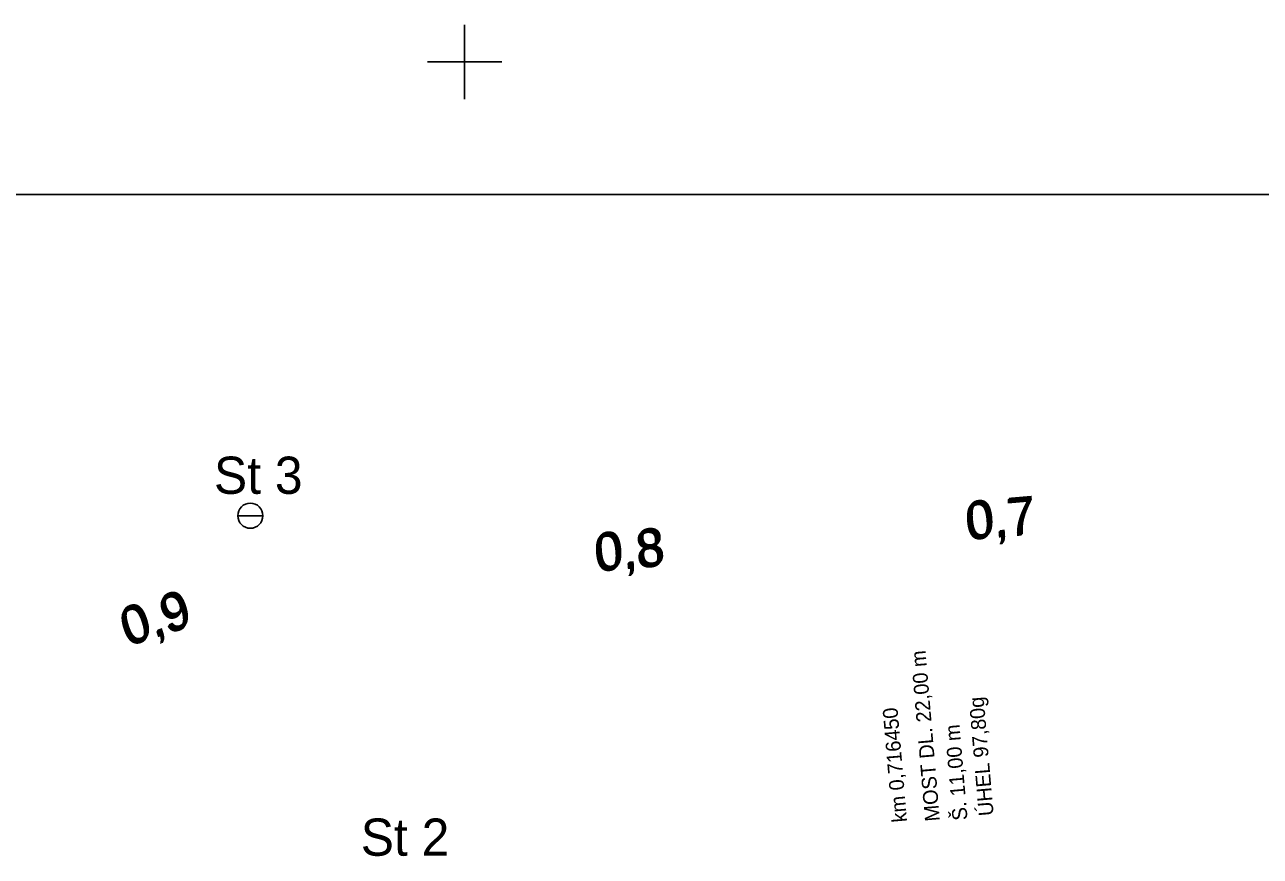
# Model space of a CAD drawing. Extents: x -606444 to -604546, y -1158114 to -1156869.
# Drawn here: x -605712.4 to -605380.6, y -1157092.1 to -1156868.7 of the extents above; entities that cross this region are included whole.
import ezdxf

# ---------------------------------------------------------------- set-up
doc = ezdxf.new("R2010")
doc.units = 0
for name, color, linetype in [('FORMAT', 7, 'Continuous'), ('Level 35', 7, 'Continuous'), ('NS_VB_POP', 7, 'Continuous'), ('OSAPOP', 7, 'Continuous'), ('ramecek_tisk', 7, 'Continuous'), ('studny', 7, 'Continuous')]:
    doc.layers.add(name, color=color, linetype=linetype)

# ---------------------------------------------------------------- blocks, each defined once
blk = doc.blocks.new('8.11')
at = {"layer": 'Level 35'}
blk.add_line((-0.0375, 0), (0.0375, 0), dxfattribs=at)
blk.add_circle((0, 0), 0.0375, dxfattribs=at)

msp = doc.modelspace()

# ---------------------------------------------------------------- linework, layer by layer
at = {"layer": 'FORMAT'}
for p, q in [((-605594.31, -1156888.73), (-605594.31, -1156868.73)), ((-605604.31, -1156878.73), (-605584.31, -1156878.73))]:
    msp.add_line(p, q, dxfattribs=at)
at = {"layer": 'ramecek_tisk'}
msp.add_line((-606362.25, -1156914.34), (-604562.25, -1156914.34), dxfattribs=at)

# ---------------------------------------------------------------- block references
at = {"layer": 'studny', "xscale": 90, "yscale": 90}
msp.add_blockref('8.11', (-605651.85, -1157000.63), dxfattribs=at)

# ---------------------------------------------------------------- texts
at = {"layer": 'NS_VB_POP'}
for s, p in [('MOST DL. 22,00 m', (-605466.66, -1157082.57)), ('ÚHEL 97,80g', (-605452.23, -1157081.11)), ('km 0,716450', (-605475.47, -1157082.82)), ('Š. 11,00 m', (-605459.24, -1157082.32))]:
    msp.add_text(s, height=4, rotation=94.8613, dxfattribs=at).set_placement(p)
at = {"layer": 'OSAPOP'}
for s, rotation, p in [('0,7', 4.8613, (-605459.47, -1157007.23)), ('0,7', 4.8613, (-605459.33, -1157007.07)), ('0,7', 4.8613, (-605459.2, -1157006.91)), ('0,7', 4.8613, (-605459.06, -1157006.75)), ('0,8', 4.8613, (-605558.84, -1157015.38)), ('0,8', 4.8613, (-605558.7, -1157015.22)), ('0,8', 4.8613, (-605559.11, -1157015.71)), ('0,8', 4.8613, (-605558.98, -1157015.54)), ('0,9', 17.6766, (-605684.9, -1157035.88)), ('0,9', 17.6766, (-605684.8, -1157035.69)), ('0,9', 17.6766, (-605684.7, -1157035.5)), ('0,9', 17.6766, (-605684.6, -1157035.31))]:
    msp.add_text(s, height=10, rotation=rotation, dxfattribs=at).set_placement(p)
at = {"layer": 'studny'}
for s, p in [('St 3', (-605661.62, -1156994.75)), ('St 2', (-605622.2, -1157091.96))]:
    msp.add_text(s, height=10, dxfattribs=at).set_placement(p)

doc.saveas('drawing.dxf')
